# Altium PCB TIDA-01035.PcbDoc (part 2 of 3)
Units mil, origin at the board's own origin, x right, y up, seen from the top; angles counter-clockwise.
Board outline 3937.01 x 2952.76 mil, 4 copper layers (Top Layer, GND, PWR, Bottom Layer), stack 79.834 mil thick; 286 components, 165 nets, 861 pads, 352 vias.
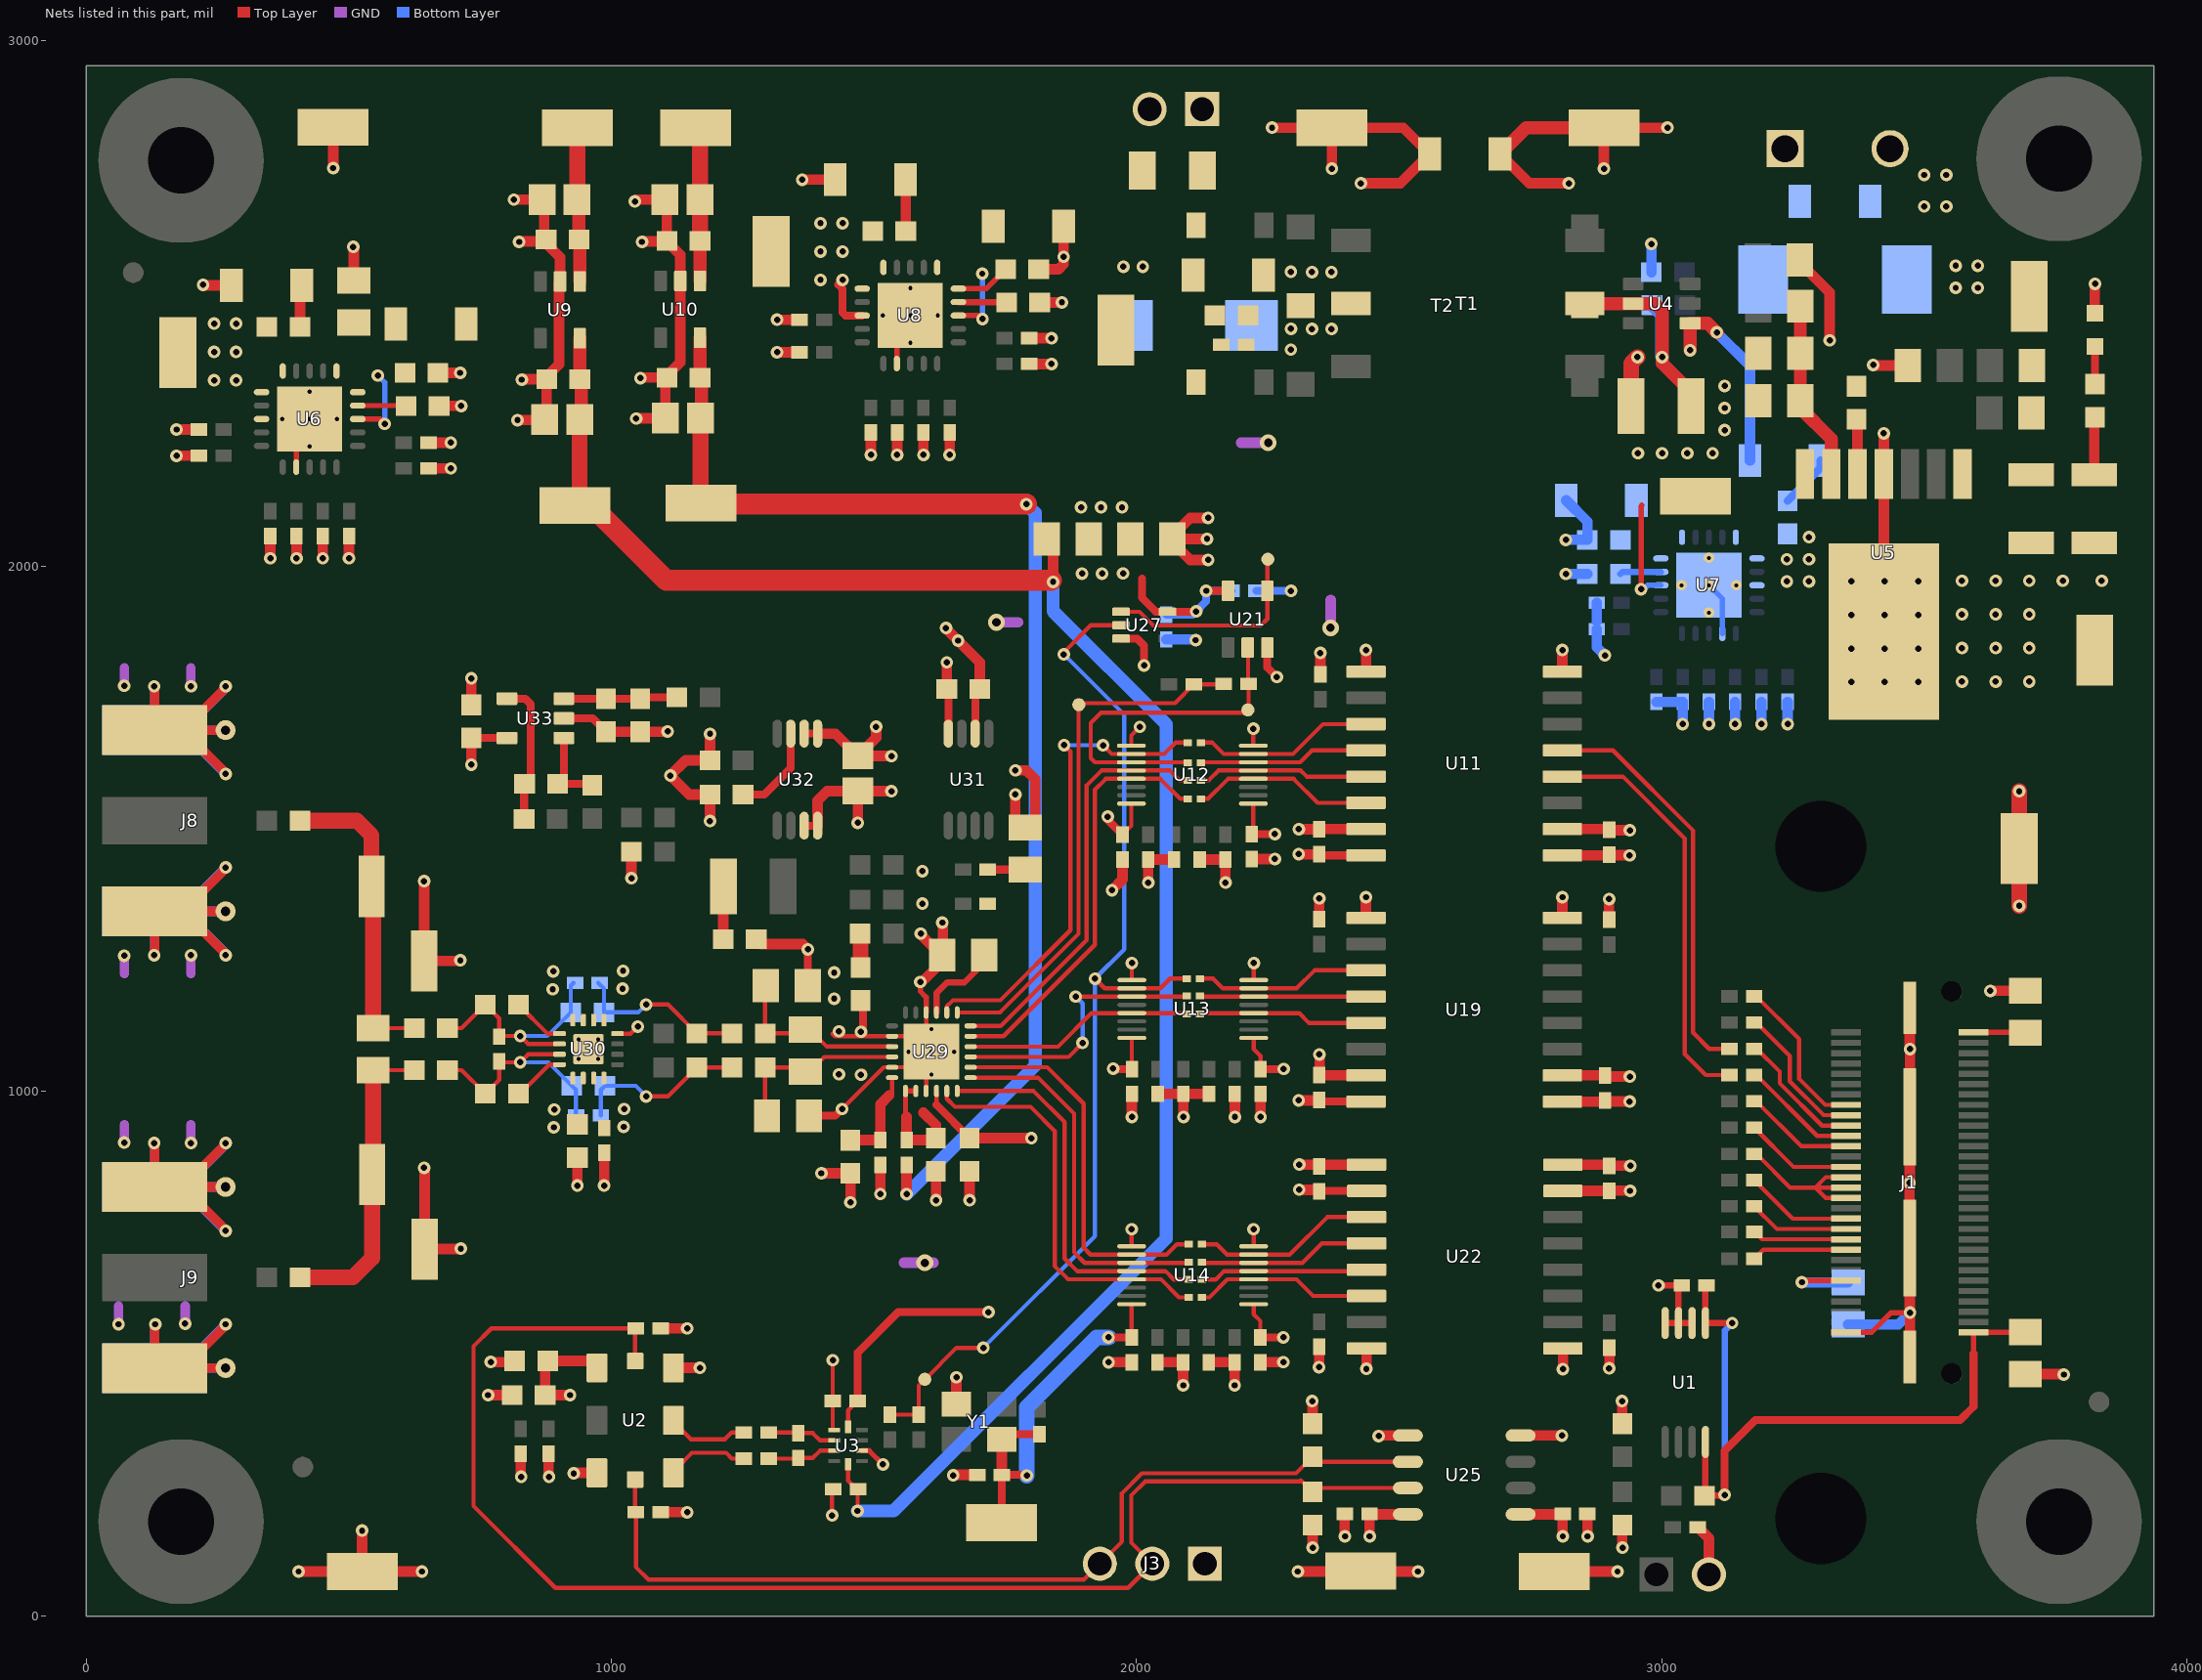
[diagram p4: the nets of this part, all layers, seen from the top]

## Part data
C1 C4 C5 C19 C88 C96: "CAP, CERM, 10 µF, 10 V, +/- 10%, X7R, 0805"
C2 C3 C6 C11 C12 C18 C44 C45 C46 C47 C48 C49 C50 C51 C58 C59 C64 C67 C68 C73 C74 C77 C90: "CAP, CERM, 0.1 µF, 16 V, +/- 10%, X7R, 0402"
C7 C97: "CAP, CERM, 0.1 µF, 25 V, +/- 5%, X7R, 0603"
C8 C89: "CAP, CERM, 10 µF, 10 V, +/- 10%, X7T, 0603"
C9 C10: "CAP, CERM, 0.1 µF, 25 V, +/- 10%, X5R, 0402"
C13: library part 293D107X9020E2TE3, "100µF ±10% Molded Tantalum Capacitors 20V 2917 (7343 Metric) 35 mOhm"
C14 C24: "CAP, CERM, 10 µF, 25 V, +/- 20%, X7R, 1206_190"
C15 C25 C28 C30 C32 C33: "CAP, CERM, 47 µF, 25 V, +/- 20%, X5R, 1206_190"
C16 C29 C31 C82 C86: "CAP, CERM, 1000 pF, 50 V, +/- 1%, C0G/NP0, 0603"
C17 C26 C34 C35 C79 C80 C92 C94 C95 C100 C101: "CAP, CERM, 1 µF, 25 V, +/- 10%, X7R, 0603"
C20: "CAP, CERM, 0.022uF, 50V, +/-10%, X7R, 0805"
C21: library part C3225X5R1A226M, "CAP, CERM, 22uF, 10V, +/-20%, X5R, 1210"
C22 C23: library part UMK325AB7106KM-T, "10µF ±10% 50V Ceramic Capacitor X7R 1210 (3225 Metric)"
C27: "CAP, CERM, 0.01uF, 50V, +/-5%, X7R, 0603"
C36 C40: "CAP, CERM, 1uF, 50V, +/-10%, X7R, 0805"
C37 C39 C41 C43: "CAP, CERM, 0.1uF, 50V, +/-10%, X7R, 0603"
C38 C42: "CAP, CERM, 10uF, 16V, +/-20%, X5R, 0805"
C75: "CAP, CERM, 1000 pF, 2000 V, +/- 10%, X7R, 1206_190"
C76 C83 C93: "CAP, CERM, 100 pF, 50 V, +/- 5%, C0G/NP0, 0402"
C81 C91: "CAP, CERM, 470 pF, 100 V, +/- 5%, C0G/NP0, 0805"
C84: "CAP, CERM, 0.01 µF, 100 V, +/- 1%, C0G/NP0, 0805"
C85: "CAP, CERM, 1000 pF, 100 V, +/- 5%, C0G/NP0, 0805"
C87: "CAP, CERM, 22 µF, 6.3 V, +/- 20%, X5R, 0603"
C98: "CAP, CERM, 47 µF, 10 V, +/- 10%, X7R, 1210"
C99: "CAP, CERM, 10uF, 10V, +/-10%, X7R, 0805"
C102: "CAP, CERM, 1uF, 10V, +/-10%, X7R, 0603"
D1 D3: "Diode, Schottky, 20 V, 0.5 A, SOD-123"
D2: "Diode, Schottky, 200V, 4A, SMC"
D4: "LED, Red, SMD"
FID1 FID2 FID3 FID4 FID5 FID6: "Fiducial mark.  There is nothing to buy or mount."
H1 H2 H3 H4: library part "NY PMS 440 0025 PH", "Machine Screw, Round, #4-40 x 1/4, Nylon, Philips panhead"
H5 H6 H7 H8: "Standoff, Hex, 0.5\"L #4-40 Nylon"
H13 H14: "ROUND STANDOFF M3 STEEL 11MM"
J1: library part QTH-030-01-L-D-A, "Header(Shrouded), 19.7mil, 30x2, Gold, SMT"
J2 J4: "Header, 2.54 mm, 2x1, Gold, TH"
J3: "Header, 2.54 mm, 3x1, Gold, TH"
J5: library part 691213510002, "2 Position Wire to Board Terminal Block Horizontal with Board 0.197\" (5.00mm) Through Hole"
J7 J11: library part 87898-0204, "Header, 2.54 mm, 2x1, Gold, R/A, SMT"
J8 J9: "Connector, End launch SMA, 50 ohm, SMT"
Logo1: library part ESD_Susceptible, "ESD Susceptible Symbol"
Logo2: library part Pb-Free
Logo3: library part FCC_disclaimer, "FCC_disclaimer"
R1 R2 R3 R4 R5 R7 R8 R9 R10 R11 R12 R27 R28 R29 R30 R32 R33 R35 R37 R41 R42 R43 R44 R45 R46 R47 R48 R49 R50 R51 R52 R53 R54 R55 R56 R81 R87 R91 R102: "RES, 0, 5%, 0.063 W, 0402"
R6: "RES, 10.0 k, 1%, 0.1 W, 0603"
R13 R14 R17: "RES, 33, 5%, 0.063 W, 0402"
R15 R16 R20 R21: "RES, 4.7 k, 5%, 0.063 W, 0402"
R18 R59 R64 R65 R69 R70 R90 R105 R106 R107 R108 R109 R110 R111 R112 R113 R114 R115: "RES, 10.0 k, 1%, 0.1 W, 0402"
R19: "RES, 100, 1%, 0.063 W, 0402"
R22: "RES, 0, 5%, 0.25 W, 1206"
R23 R38 R39: "RES, 0.1, 1%, 0.1 W, 0603"
R24: "RES, 118 k, 1%, 0.125 W, 0805"
R25: library part RT0805BRD075K62L, "RES, 5.62 k, 0.1%, 0.125 W, 0805"
R26: "RES, 249k ohm, 1%, 0.125W, 0805"
R31: "RES, 549, 0.5%, 0.1 W, 0805"
R34: "RES, 20.5 k, 1%, 0.125 W, 0805"
R36: "RES, 392, 0.5%, 0.1 W, 0805"
R40: "RES, 1.2 k, 5%, 0.1 W, 0603"
R57 R58 R60 R61 R62 R63 R66 R67 R68 R71 R76: library part CRCW04020000Z0ED, "RES SMD 0.0OHM JUMPER 1/20W 0201"
R72 R73 R74 R75: "RES, 1.5 k, 5%, 0.1 W, 0603"
R77 R82 R83 R92: "RES, 1.00 k, 0.1%, 0.1 W, 0603"
R78 R80 R84 R86 R88 R98 R103 R104: "RES, 0, 5%, 0.1 W, 0603"
R79 R89: library part RT0603BRD0722R1L, "RES SMD 22.1 OHM 0.5% 1/16W 0603"
R85: "RES, 1.00, 1%, 0.1 W, 0603"
R93: "RES, 0.22, 1%, 0.125 W, 0402"
R94: "RES, 20.0 k, 0.1%, 0.1 W, 0603"
R95: "RES, 1.00 k, 1%, 0.1 W, 0603"
R96: "RES, 499, 0.1%, 0.1 W, 0603"
R97 R101: "RES, 49.9 k, 0.1%, 0.1 W, 0603"
R99 R100: "RES, 0.22 ohm, 1%, 0.1W, 0603"
R116 R117: "RES, 0, 5%, 0.125 W, 0805"
T1: "Transformer, 340 uH, TH"
T2: "Transformer, 110 uH, SMT"
TP1 TP20 TP21 TP22: "Test Point, O.025\""
TP2 TP3 TP4 TP5 TP6 TP7 TP8 TP9 TP10 TP11 TP12 TP13 TP14 TP15 TP16 TP17 TP18 TP19: "Test Point, Miniature, SMT"
U1: "I2C BUS EEPROM (2-Wire), TSSOP-B8"
U2: library part LMK61E2-SIAR, "Ultra-Low Jitter Programmable Oscillator with Internal EEPROM, SIA0008B"
U3: "500 Mbps High-Speed Differential Line Driver / Receivers with LVDS Input and LVTTL / LVCMOS Output, 1 Rx, -40 to +85 degC, 10-pin UQFN (RSE), Green (RoHS & no Sb/Br)"
U4: "LOW-NOISE 1A TRANSFORMER DRIVERS FOR ISOLATED POWER SUPPLIES, DBV0006A"
U5: "3A SIMPLE SWITCHER® Power Module with 42V Maximum Input Voltage, 7-pin TO-PMOD, Pb-Free"
U6 U7 U8: "36-V, 1-A, 4.17-µVRMS, RF LDO Voltage Regulator, RGW0020A"
U9 U10: library part TPS70933DBVT, "IC REG LDO 1.8V 0.15A SOT23-5"
U11 U22: library part ISO7840DWR, "High-Performance, 8000 VPK Reinforced Quad-Channel Digital Isolator, DW0016B"
U12 U13 U14: "4-Bit Dual-supply Bus Transceiver with Configurable Voltage Translation and 3-State Outputs, DGV0016A"
U19: "High-Performance, 8000 VPK Reinforced Quad Channel Digital Isolator, DW0016B"
U21: "SINGLE SCHMITT-TRIGGER INVERTER GATE, DBV0005A"
U25: "Low-Power Bidirectional I2C Isolators, D0008A"
U27: library part SN74AUP1G80DCK, "IC, Single Positive-Edge-Triggered D-Type Flip-Flop"
U29: library part ADS9110IRGER, "18-Bit, 2-MSPS, 20-mW, SAR ADC with Enhanced Serial Interface, RGE0024H"
U30: "Low Power, Precision, 160MHz, Fully Differential Amplifier, RGT0016A"
U31: "Low Noise, Very Low Drift, Precision Voltage Reference, -40 to 125 degC, 8-pin VSSOP (DGK), Green (RoHS & no Sb/Br)"
U32: library part REF6025AIDGK, "High-Precision Voltage Reference with Integrated High-Bandwidth Buffer, DGK0008A"
U33: "Precision, Low Noise, Low Iq Operational Amplifier, 2.2 to 5.5 V, -40 to 125 degC, 5-pin SOT23 (DBV0005A), Green (RoHS & no Sb/Br)"
Y1: library part AU-40.000MDE-T, "OSC, 125 MHz, 3.3V, SMD"
ZZ1 ZZ2 ZZ3: library part AssemblyNote

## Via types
v1: diameter 24, hole 12, Top Layer to Bottom Layer, tented both sides, 324 vias
v2: diameter 19.68, hole 7.87, Top Layer to Bottom Layer, 24 vias
v3: diameter 32, hole 16, Top Layer to Bottom Layer, 4 vias

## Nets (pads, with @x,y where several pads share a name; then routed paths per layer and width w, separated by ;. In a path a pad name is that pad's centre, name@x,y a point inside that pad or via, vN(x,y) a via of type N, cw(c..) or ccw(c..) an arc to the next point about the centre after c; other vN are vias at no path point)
1P8V_ISO: C11.1 C38.1 C39.1 R117.2 TP8.1 U3.5 U9.5 | length 3618.5
  Top Layer w8: U3.5@1450.51,289.57 1450.51,258.11 1468.62,240 v1(1468.62,200.38)
  Top Layer w20: R117.2@1829.18,2051.77 1841,2039.95 v1(1841,1970) v1@1838,1973
  Top Layer w25: C39.1@939.4,2356.09 U9.5@939.4,2433.87 ; C38.1@942.56,2279.34 C39.1@942.56,2355.37
  Top Layer w30: C38.1@939.46,2279 939.46,2124.46 TP8.1@930,2115 TP8.1@962,2115
  Top Layer w40: TP8.1@962,2115 1104,1973 v1@1838,1973
  Bottom Layer w25: v1(1468.62,200.38) 1537.38,200.38 2056.18,719.18 2056.18,1698.77 1841,1913.95 v1(1841,1970)
3P3V: C44.2 C58.2 C68.1 C73.2 R38.2 R64.1 R69.2 R72.2 R74.2 TP6.1 U7.1 U7.3 U7.20 U11.1 U19.1 U22.16 U25.1 | length 898.7
  Top Layer w15: C68.1@2898.62,860 C68.1@2901,857.62
  Top Layer w20: U25.1@2731.28,194 2810.38,194 C73.2@2811.38,195 2811.38,151.62 v1(2811.76,152) ; U19.1@2811.01,980 2899.62,980 2900,980.38 2938.62,980.38 v1(2939,980) ; U11.1@2811.01,1449 2899.62,1449 2900,1449.38 2938.62,1449.38 v1(2939,1449) ; U22.16@2812.01,860 C68.1@2898.62,860 ; v1(2900,472) 2900.38,472.38 2900.38,511 R69.2@2900,511.38 ; R64.1@2900,1326.62 2899.62,1327 2899.62,1365.62 v1(2900,1366) ; C68.1@2901,857.62 2901.38,858 2940,858 v1(2940.38,857.62) ; R74.2@2924,367.5 R74.2@2925,366.5 2925,409.87 v1(2924.62,409.5) ; v1(2925.38,130.5) 2925,130.13 R72.2@2925,173.5 R72.2@2926,172.5
  Top Layer w30: v1(3681,1353) TP6.1@3681,1462 v1(3681,1571)
  other v1: 3238.5,1971 3280.5,1971 3238.5,2013 3280.5,2013 3280.5,2055
3P3V_ISO: C7.1 C8.1 C45.1 C46.1 C48.1 C50.1 C59.1 C67.2 C74.1 R15.2 R16.2 R18.2 R21.1 R39.2 R59.2 R65.2 R70.1 R73.2 R75.2 R105.2 R108.2 R116.2 TP7.1 U2.1@972.17,473 U2.6@1117.83,473 U8.1 U8.3 U8.20 U11.16 U12.1 U13.1 U14.1 U19.16 U22.1 U25.8 | length 1925.8
  Top Layer w8: C46.1@2219.18,1489.39 2222.32,1492.54 U12.1@2222.32,1547.65 ; U14.1@2222.82,594.15 2222.82,575.13 2235.68,562.27 C50.1@2235.68,530.89 ; U13.1@2223.18,1101.28 2223.18,1079.77 2236.04,1066.91 C48.1@2236.04,1042.02
  Top Layer w15: 1432,2536 1440,2528 1440,2483 1445.73,2477.27 U8.3@1477.46,2477.27 ; C46.1@2219.18,1489.39 v1@2263.05,1489.39 ; C50.1@2235.68,530.89 v1@2279.55,530.89 ; C48.1@2236.04,1042.02 v1@2279.91,1042.02 ; C59.1@2348,982.38 2350.38,980 U19.16@2436.99,980 ; C45.1@2348,1451.38 2350.38,1449 U11.16@2436.99,1449
  Top Layer w20: R21.1@827,309.38 827,266.21 v1(828,265.21) ; v1(921,421) C7.1@873.5,421 873.5,481 C8.1@878.5,486 959.17,486 U2.1@972.17,473 ; R16.2@1093.62,198 v1(1144,198) ; R15.2@1093.62,548 v1(1144,548) ; U2.6@1117.83,473 v1(1168.21,473) ; R18.2@2120.18,1441.15 R105.2@2169.18,1441.15 2169.18,1397.28 v1(2169.32,1397.14) ; v1(2134.18,2051.77) R116.2@2068.18,2051.77 ; v1(2136.18,2011.77) 2102.18,2011.77 2068.18,2045.77 R116.2@2068.18,2051.77 ; v1(2136.18,2091.77) 2102.18,2091.77 2068.18,2057.77 R116.2@2068.18,2051.77 ; R108.2@2187.04,994.78 2187.04,950.91 v1(2187.18,950.77) ; v1@2263.05,1489.39 v1(2263.19,1489.54) ; v1@2279.55,530.89 v1(2279.69,531.04) ; v1@2279.91,1042.02 v1(2280.05,1042.17) ; v1(2308.62,982.38) 2309,982 2347.62,982 C59.1@2348,982.38 ; v1(2308.62,1451.38) 2309,1451 2347.62,1451 C45.1@2348,1451.38 ; v1(2310,860) 2310.38,859.62 2349,859.62 2349.38,860 U22.1@2437.99,860 ; R73.2@2334,367.5 R73.2@2335,366.5 2335,409.87 v1(2334.62,409.5) ; v1(2335.38,130.5) 2335,130.13 R75.2@2335,173.5 R75.2@2336,172.5 ; v1(2347.62,474.38) 2348,474.76 R70.1@2348,513.38 R70.1@2347.62,513.76 ; R65.2@2348,1327.62 2347.62,1328 2347.62,1366.62 v1(2348,1367) ; R59.2@2350,1793.62 v1(2350,1834.63) ; v1(2444,152) 2443.62,151.62 C74.1@2443.62,195 2444.62,194 U25.8@2516.72,194
  other v1: 1398,2545 1440,2545 1398,2599 1440,2599 1398,2653 1440,2653
5V_ISO: C89.1 C90.2 C94.1 C97.2 C99.2 R23.2 R91.2 TP2.1 U6.1 U6.3 U6.20 U30.5 U30.6 U30.7 U30.8 U30.12 U31.2 U32.1 U32.2 U33.5 | length 703.8
  Top Layer w8: U30.12@1011.12,1109.53 1036.53,1109.53 v1(1050,1123)
  Top Layer w15: v1(732.94,1621.94) v1@733,1622 ; C97.2@733,1672.5 733.09,1672.6 U33.5@800.87,1672.6 ; U32.2@1366.86,1680.88 U32.1@1392.45,1680.88 ; U31.2@1692.65,1680.88 1692.65,1757.15 C94.1@1701.5,1766
  Top Layer w20: v1@733,1622 C97.2@733,1672.5 ; U32.1@1392.45,1680.88 1426.58,1680.88 C99.2@1469,1638.46 ; v1(1504,1694) 1504,1673.46 C99.2@1469,1638.46 ; v1(1512,804) R91.2@1512,859.38 ; v1(1533,1638) 1532.54,1638.46 C99.2@1469,1638.46 ; v1(1637,1882) 1637,1881 v1(1660,1858) 1701.5,1816.5 C94.1@1701.5,1766
  other v1: 890,931 1023,932 891,965 1024,966 243.07,2353.86 285.07,2353.86 243.07,2407.86 285.07,2407.86 243.07,2461.86 285.07,2461.86
5VDC: C20.1 C21.1 C28.1 C29.1 R25.2 R103.2 T1.2 T2.2 TP5.1 U4.2 U5.7 U7.13 U7.15 U7.16 | length 665
  Top Layer w10: v1(2961,1956) 2961,2115 2962,2116
  Top Layer w25: T1.2@2853.64,2500 U4.2@2945.87,2500 2987,2500 3001,2486 v1(3001,2398) 3001,2386.15 3056.09,2331.06 C21.1@3056.09,2305
  Bottom Layer w10: v1(2961,1956) 2966,1956 2973.35,1963.35 U7.13@2998.46,1963.35
  Bottom Layer w25: R103.2@2981.5,2497 3000,2478.5 3000,2399 v1(3001,2398)
  other v1: 2955,2215 3001,2215 3049,2215 3097,2215 3120,2259 3120,2301 3120,2343
+12VDC: C22.1 C23.1 D2.1 R24.2 R26.2 R40.2 TP4.1 U5.1 | length 110
  Top Layer w20: C23.1@3824,2173.96 3824,2282.5 R40.2@3825,2283.5
  other v1: 3560,2530 3602,2530 3560,2572 3602,2572
+12VDC_IN: C24.1 D2.2 J5.1
A1P8V_ISO: C42.1 C43.1 R81.1 TP9.1 U10.5 | length 2412.8
  Top Layer w20: TP9.1@1169.46,2120.54 TP9.1@1170,2120 TP9.1@1172,2118 ; v1(1562,804) R81.1@1562,859.38
  Top Layer w25: C43.1@1168.4,2359.09 U10.5@1168.4,2434.87 ; C42.1@1171.56,2282.34 C43.1@1171.56,2358.37
  Top Layer w30: TP9.1@1169.46,2120.54 C42.1@1169.46,2282
  Top Layer w40: TP9.1@1172,2118 v1(1790,2118)
  Bottom Layer w25: v1(1562,804) 1807,1049 1807,2101 v1(1790,2118)
ADC_CONVST: R62.2 R87.2 TP22.1 U12.11 U21.2 | length 684.7
  Top Layer w8: R62.2@2097.68,1625.77 2097.06,1626.39 U12.11@1990.04,1626.39 1920.56,1626.39 1912.68,1634.27 1912.68,1701.27 1932.18,1720.77 2206.77,1720.77 TP22.1@2212,1726 2213.2,1727.2 R87.2@2213.2,1775.91 2212.23,1775.91 U21.2@2212.23,1844.13
ADC_CONVST1: R87.1 R102.1 TP21.1 U29.1 | length 1022.5
  Top Layer w8: U29.1@1658.28,1149.74 1739.74,1149.74 1889.5,1299.5 1889.5,1735.5 TP21.1@1890,1736 1892.77,1738.77 2073.07,1738.77 R102.1@2109.2,1774.91 2164.96,1774.91 R87.1@2165.96,1775.91
ADC_CONVSTN: TP20.1 U21.4 U27.1 | length 408.6
  Top Layer w8: U27.1@1970.42,1913 2005.49,1913 2031.58,1886.91 2236.58,1886.91 2248.98,1899.31 U21.4@2248.98,1953.04 2248.98,2011.98 TP20.1@2250,2013
ADC_CSN: R68.2 U12.12 U29.24 | length 795.7
  Top Layer w8: U29.24@1683.87,1124.15 1741.15,1124.15 1905,1288 1905,1582.59 1933.06,1610.65 U12.12@1990.04,1610.65 2063.31,1610.65 2082.18,1591.77 R68.2@2097.68,1591.77
ADC_RESETN: R57.2 U12.10 U29.2 | length 916.3
  Top Layer w8: U29.2@1638.59,1149.74 1638.59,1161.59 1650.05,1173.05 1665,1173.05 1665.05,1173 1740.37,1173 1874,1306.63 1874,1647 v1(1862,1659) ; v1(1936.18,1658.77) 1952.81,1642.14 U12.10@1990.04,1642.14 2052.55,1642.14 2074.18,1663.77 R57.2@2097.68,1663.77
  Bottom Layer w8: v1(1862,1659) 1862.23,1658.77 v1(1936.18,1658.77)
ADC_RVS: R76.2 U13.11 U29.21 | length 530.2
  Top Layer w8: U29.21@1683.87,1065.09 1870.5,1065.09 v1(1897.18,1091.77) ; v1(1884.02,1180.02) U13.11@1990.9,1180.02 2094.16,1180.02 R76.2@2095.54,1181.4
  Bottom Layer w8: v1(1884.02,1180.02) 1897.18,1166.87 v1(1897.18,1091.77)
ADC_SCLK: R60.2 U12.13 U29.23 | length 805.9
  Top Layer w8: U29.23@1683.87,1104.46 1746.46,1104.46 1920.5,1278.5 1920.5,1574.09 1941.31,1594.9 U12.13@1990.04,1594.9 2045.06,1594.9 2083.18,1556.77 R60.2@2097.68,1556.77
ADC_SDI: R67.2 U13.13 U29.22 | length 438.5
  Top Layer w8: U29.22@1683.87,1084.78 1850.19,1084.78 1913.94,1148.53 U13.13@1990.9,1148.53 2094.41,1148.53 R67.2@2095.54,1147.4
ADC_SDO0: R66.2 U14.10 U29.20 | length 731.7
  Top Layer w8: U29.20@1683.87,1045.41 1829.59,1045.41 1899,976 1899,702 1912.36,688.64 U14.10@1990.54,688.64 2057.05,688.64 2076.68,708.27 R66.2@2099.18,708.27
ADC_SDO1: R58.2 U14.11 U29.19 | length 716.7
  Top Layer w8: U29.19@1683.87,1025.72 1812.28,1025.72 1881,957 1881,693 1901.11,672.89 U14.11@1990.54,672.89 2097.8,672.89 R58.2@2099.18,674.27
ADC_SDO2: R61.2 U14.12 U29.18 | length 741.9
  Top Layer w8: U29.18@1658.28,1000.13 1803.87,1000.13 1863,941 1863,681 1886.85,657.15 U14.12@1990.54,657.15 2054.81,657.15 2070.68,641.27 R61.2@2099.18,641.27
ADC_SDO3: R63.2 U14.13 U29.17 | length 782.5
  Top Layer w8: U29.17@1638.59,1000.13 1638.59,985.41 1654,970 1798,970 1844,924 1844,667 1869.6,641.4 U14.13@1990.54,641.4 2046.56,641.4 2080.68,607.27 R63.2@2099.18,607.27
ADC_SYSCLK: R14.2 R17.2 R71.2 TP1.1 U13.10 U27.2 | length 2068.6
  Top Layer w8: R17.2@1530,383.62 R14.2@1585,383.62 1585,439.36 TP1.1@1596.64,451 ; TP1.1@1597,451 1657,511 v1(1708,511) ; v1(1861.18,1831.77) 1861.18,1835.77 1912.82,1887.41 U27.2@1970.42,1887.41 ; v1(1920.68,1214.27) 1939.18,1195.77 U13.10@1990.9,1195.77 2045.18,1195.77 2063.81,1214.4 R71.2@2095.54,1214.4 ; U27.2@1970.42,1887.81 U27.2@1971.18,1887.81
  Bottom Layer w8: v1(1708,511) 1920.68,723.68 v1(1920.68,1214.27) 1976.68,1270.27 1976.68,1716.27 v1(1861.18,1831.77)
AGND_ISO: C6.2 C7.2 C8.2 C11.2 C12.2 C13.2 C14.2 C15.2 C16.2 C17.2 C18.1 C19.2 C25.2 C26.1 C30.2 C31.2 C33.2 C35.1 C36.2 C37.2 C38.2 C39.2 C40.2 C41.2 C42.2 C43.2 C45.2 C46.2 C47.2 C48.2 C49.2 C50.2 C51.2 C59.2 C64.1 C67.1 C74.2 C75.1 C77.1 C79.1 C80.2 C81.2 C87.2 C88.2 C89.2 C90.1 C91.2 C92.2 C94.2 C96.2 C97.1 C99.1 C100.2 C101.2 C102.2 J3.1 J7.1 J8.2 J8.3 J8.4 J8.5 J9.2 J9.3 J9.4 J9.5 J11.1 R20.1 R27.1 R28.1 R29.1 R30.1 R32.1 R33.1 R35.1 R37.1 R42.1 R44.1 R46.1 R48.1 R50.1 R52.1 R54.1 R56.1 R99.2 R100.1 R101.1 R106.1 R107.1 R109.1 R110.1 R111.1 R112.1 R113.1 R114.1 R115.1 T1.5 T2.5 TP12.1 TP13.1 TP18.1 TP19.1 U2.3@972.17,273 U3.1 U3.7 U6.7 U6.21 U8.7 U8.21 U9.2 U10.2 U11.9 U11.15 U12.8 U12.9 U13.8 U13.9 U14.8 U14.9 U19.9 U19.15 U21.3 U22.2 U22.8 U25.5 U27.3 U29.4 U29.8 U29.11 U29.15 U29.25 U30.13 U30.14 U30.15 U30.16 U30.17 U31.4 U32.7 U32.8 U33.2 Y1.2 | length 12006.7
  Top Layer w8: v1(1420,192) 1420,238.62 C11.2@1421.38,240 ; 1420.79,1109.21 1425.54,1104.46 U29.8@1534.26,1104.46 1579.54,1104.46 U29.25@1599.22,1084.78 ; C12.2@1421,409.62 C12.2@1421.38,410 ; v1(1421.38,487.62) C12.2@1421.38,410 ; U3.1@1423.94,354.53 1421.38,357.09 C12.2@1421.38,410 ; v1(1439,966) 1518.41,1045.41 U29.11@1534.26,1045.41 1579.54,1045.41 U29.25@1599.22,1065.09 ; U29.15@1599.22,1000.13 U29.25@1599.22,1065.09 ; U29.4@1599.22,1149.74 U29.25@1599.22,1084.78 ; U12.9@1990.04,1657.89 1990.04,1677.63 v1(2006.18,1693.77) ; U14.9@1990.54,704.39 v1(1990.54,736.93) ; U13.9@1990.9,1211.52 v1(1990.9,1244.06) ; U12.8@2222.32,1657.89 v1(2222.32,1690.43) ; U14.8@2222.82,704.39 v1(2222.82,736.93) ; U13.8@2223.18,1211.52 v1(2223.18,1244.06) ; U29.25@1599.22,1065.09 v2(1609.06,1074.94) U29.25@1599.22,1084.78
  Top Layer w10: U6.7@399.47,2188.53 399.47,2254.47 v2(425.06,2280.06) ; U3.7@1477.09,315.16 1490.55,315.16 1516.71,289 v1(1517,289) ; U8.7@1543.41,2385.73 U8.21@1543.41,2451.68 ; v1(1588,1208) 1588,1190.22 1599.22,1179 U29.4@1599.22,1149.74
  Top Layer w15: v1@733,1786 v1(733.06,1786.06) ; U33.2@909.13,1710 964.01,1710 C101.2@989.5,1684.5 ; v1(1037.94,1405.43) v1@1038.01,1405.5 ; v1(1187.5,1514.37) v1@1187.57,1514.43 ; v1@1187.57,1680.44 v1(1187.63,1680.5) ; U32.7@1366.86,1505.68 U32.8@1392.45,1505.68 ; C81.2@1374,1201 v1(1374,1270) ; C91.2@1376,953 1426,953 v1(1439,966) ; v1(1475,1031) v1@1479,1035 ; v1(1475,1113) 1479,1117 C87.2@1479,1172.5 ; U8.21@1543.41,2451.68 v2(1569,2477.27) ; C94.2@1638.5,1766 1641.46,1763.04 U31.4@1641.46,1680.88 ; v1@1638.5,1816.5 v1(1638.57,1816.57) ; U27.3@1970.42,1861.82 2001.13,1861.82 2014.18,1848.77 v1(2014.18,1810.77) ; U21.3@2248.98,1849.71 U21.3@2248.98,1844.77 2248.98,1806.97 v1(2267.18,1788.77) ; C67.1@2349,812.38 2351.38,810 U22.2@2437.99,810
  Top Layer w18: J9.2@130,472.5 v1@130,555 ; J9.3@130,817.5 v1@130,900 ; v1@130,1260 J8.2@130,1342.5 ; J8.3@130,1687.5 v1@130,1770 ; J9.2@183.5,472.5 265,554 v1(265,556) ; v1(265,734) 265,736 183.5,817.5 v1@265,899 ; v1@265,1261 183.5,1342.5 265,1424 v1(265,1426) ; v1(265,1604) 265,1606 183.5,1687.5 v1@265,1769
  Top Layer w20: v1(171.55,2210.06) R28.1@213.82,2210.06 ; v1(171.55,2260.06) R27.1@213.82,2260.06 ; v1(222.07,2535.86) 223.07,2534.86 C25.2@276.14,2534.86 ; v1(350.06,2014.8) R29.1@350.06,2057.06 ; v1(400.06,2014.8) R30.1@400.06,2057.06 ; v1(404,85) TP18.1@525,85 ; v1(450.06,2014.8) R32.1@450.06,2057.06 ; v1(470,2758) TP13.1@470,2836 ; v1(500.06,2014.8) R33.1@500.06,2057.06 ; v1(508,2608) 509,2607 C19.2@509,2544 ; v1(525,163) TP18.1@525,85 ; v1(639,85) TP18.1@525,85 ; v1(643,854) 644,853 J11.1@644,699.13 712.13,699.13 v1(713,700) ; v1(643,1400) J7.1@643,1248.13 711.13,1248.13 v1(712,1249) ; R35.1@651.69,2186.06 v1(693.95,2186.06) ; R37.1@651.69,2235.06 v1(693.95,2235.06) ; C16.2@669.56,2368.06 v1(711.83,2368.06) ; C26.1@671.56,2305.06 v1(713.83,2305.06) ; C97.1@733,1735.5 v1@733,1786 ; v1(765,421) C7.2@810.5,421 ; v1(770,484) 813.5,484 C8.2@815.5,486 ; v1(814,2698) C36.2@867.54,2698 871.5,2694.03 C37.2@871.5,2618.46 ; v1(820.97,2278) 821.43,2278.46 C38.2@876.5,2278.46 ; v1(823.97,2617.46) 824.97,2618.46 C37.2@871.5,2618.46 ; v1(828.97,2355) 829.97,2356 C39.2@876.5,2356 ; C37.2@871.5,2618.15 C37.2@871.5,2618.46 ; C37.2@874.47,2618.46 C37.2@871.5,2618.46 ; C37.2@875.5,2622 875.5,2614.46 902,2587.97 U9.2@902,2542.13 900,2540.13 900,2384.54 876.5,2361.05 C39.2@876.5,2356 ; C38.2@879.47,2278.46 C38.2@876.5,2278.46 ; R20.1@880,309.38 880,266.21 v1(881,265.21) ; v1(928,272) 929,273 U2.3@972.17,273 ; v1(935,820) C89.2@935,873.5 ; v1(986,820) C90.1@986,882.38 ; C101.2@989.5,1684.5 R101.1@1054.5,1684.5 1106.5,1684.5 v1(1107,1685) ; v1@1038.01,1405.5 C100.2@1038.01,1456 ; v1(1044.46,2694.46) 1048,2698 C40.2@1101.54,2698 1105.5,2694.03 C41.2@1105.5,2619 C41.2@1105.5,2618.46 ; v1(1047,2281) 1047.46,2281.46 C42.2@1102.54,2281.46 ; v1(1055,2358) 1056,2359 C43.2@1102.54,2359 ; v1(1057.97,2617.46) 1058.97,2618.46 C41.2@1105.5,2618.46 ; C42.2@1105.5,2281.46 C42.2@1102.54,2281.46 ; C43.2@1105.5,2359 C43.2@1102.54,2359 ; C41.2@1108.47,2618.46 C41.2@1105.5,2618.46 ; v1@1187.57,1514.43 C102.2@1187.57,1564.94 1148.06,1564.94 v1(1112,1601) 1140.94,1629.94 R100.1@1187.57,1629.94 v1@1187.57,1680.44 ; R99.2@1275.5,1289 1284.5,1280 1364,1280 v1(1374,1270) ; v1(1315.49,2407.27) R44.1@1357.76,2407.27 ; v1(1315.49,2469.27) R42.1@1357.76,2469.27 ; v1(1363,2736) C33.2@1426.07,2736 ; U32.8@1392.45,1505.68 1392.45,1553.45 1410.54,1571.54 C99.1@1469,1571.54 ; v1(1399.62,843.5) C92.2@1455,843.5 v1(1455,788.13) ; v1(1469,1511) C99.1@1469,1571.54 ; v1(1494,2212) R46.1@1494,2254.27 ; v1(1533,1571.07) 1532.54,1571.54 C99.1@1469,1571.54 ; v1(1544,2212) R48.1@1544,2254.27 ; v1(1588,1208) 1591.22,1208 1631,1247.78 C88.2@1631,1256 ; v1@1590,1297 C88.2@1631,1256 ; v1(1594,2212) R50.1@1594,2254.27 ; v1(1618,792.13) C80.2@1618,847.5 ; v1@1631,1318 C88.2@1631,1256 ; C94.2@1638.5,1766 v1@1638.5,1816.5 ; v1(1644,2212) R52.1@1644,2254.27 ; v1(1650.69,268.31) 1651.69,269.31 1696.06,269.31 C6.2@1696.38,269 ; Y1.2@1656.69,403.46 1656.69,454.69 v1(1657,455) ; v1(1682,792.13) C79.1@1682,847.5 ; v1(1769,1565) 1769,1521 C96.2@1788,1502 1807,1521 1807,1594 1790,1611 v1(1769,1611) ; R54.1@1795.62,2385 v1(1837.89,2385) ; R56.1@1795.62,2434 v1(1837.89,2434) ; C31.2@1813.5,2565.27 1851.27,2565.27 1861,2575 v1(1861,2589) 1861,2647.2 C30.2@1860.93,2647.27 ; C35.1@1815.5,2502.27 v1(1857.76,2502.27) ; v1(1946.67,483.51) 1946.82,483.65 C51.2@1990.68,483.65 ; v1(1953.18,1382.77) 1973.18,1402.77 C47.2@1973.18,1441.15 ; C49.2@1991.04,994.78 1991.04,950.91 v1(1991.18,950.77) ; v1(2022.32,1397.14) 2022.18,1397.28 R106.1@2022.18,1441.15 R107.1@2071.18,1441.15 ; R112.1@2039.68,483.65 R113.1@2088.68,483.65 2088.68,439.78 v1(2088.82,439.64) ; R109.1@2040.04,994.78 R110.1@2089.04,994.78 ; v1(2089.18,950.77) 2089.04,950.91 R110.1@2089.04,994.78 ; R115.1@2137.68,483.65 R114.1@2186.68,483.65 2186.68,439.78 v1(2186.82,439.64) ; R111.1@2138.04,994.78 R110.1@2089.04,994.78 ; C46.2@2219.18,1442.15 2263.05,1442.15 v1(2263.19,1442.29) ; C50.2@2235.68,483.65 2279.55,483.65 v1(2279.69,483.79) ; C48.2@2236.04,994.78 2236.04,950.91 v1(2236.18,950.77) ; v1(2258,2835) TP12.1@2372,2835 ; v1(2307,85) TP19.1@2428,85 ; v1(2309,1499) 2309.38,1498.62 C45.2@2348,1498.62 2348.38,1499 U11.15@2436.99,1499 ; v1(2309.62,812.38) 2310,812 2348.62,812 C67.1@2349,812.38 ; C59.2@2347.62,1031 C59.2@2348,1030.62 ; v1@2347.62,1069.62 v1(2348,1070) 2348.62,1069.38 C59.2@2348.62,1031 ; C59.2@2348.38,1030 U19.15@2436.99,1030 ; v1(2372,2757) TP12.1@2372,2835 ; v1(2396.76,152) 2396.38,151.62 C74.2@2396.38,195 C74.2@2397.38,194 ; TP19.1@2427,86 TP19.1@2428,85 ; v1(2427,2729) 2502.07,2729 C75.1@2558.07,2785 2508.07,2835 TP12.1@2372,2835 ; U19.9@2436.99,1330 2436.61,1330.38 2436.61,1369 v1(2436.99,1369.38) ; U11.9@2436.99,1799 v1(2436.99,1840.01) ; v1(2437.61,471) 2437.99,471.38 U22.8@2437.99,510 U22.8@2437.61,510.38 ; v1(2461,343) 2462,344 U25.5@2516.72,344 U25.5@2517.09,344.38 ; v1(2536,85) TP19.1@2428,85 ; C38.2@876.5,2278.46 C39.2@876.5,2356 ; C42.2@1102.54,2281.46 C42.2@1102.54,2282 C43.2@1102.54,2359 ; C43.2@1102.54,2359 1102.54,2359.54 1131,2388 U10.2@1131,2543.13 1131,2592.65 1105.5,2618.15 C41.2@1105.5,2618.46
  GND w18: v1(61,556) 61,591 ; v1(72,902) 72,936 ; 72,1224 v1(72,1258) ; v1(72,1772) 72,1806 ; v1(188,557) 188,591 ; v1(199,901) 199,936 ; 199,1224 v1(199,1259) ; v1(199,1771) 199,1806
  GND w20: 1557,673 v3(1596.64,673) 1613,673 ; v3(1733.02,1892.98) 1773.98,1892.98 ; 2199,2235 v3(2250.71,2235) ; v3(2369.48,1882.48) 2369.48,1935.48
  Bottom Layer w15: C64.1@2228.2,1952.91 2294.05,1952.91 v1(2294.18,1952.77)
  Bottom Layer w18: v1(129,901) 130,900 J9.5@130,817.5 ; v1(129,1259) 130,1260 J8.4@130,1342.5 ; v1(129,1771) 130,1770 J8.5@130,1687.5 ; J9.4@130,472.5 130,555 v1(131,556) ; J9.4@181.5,472.5 v1(265,556) ; J9.5@181.5,817.5 v1(265,734) ; J8.4@181.5,1342.5 v1(265,1426) ; J8.5@181.5,1687.5 v1(265,1604) ; J9.5@184.5,817.5 v1@265,898 ; J8.4@184.5,1342.5 v1@265,1262 ; J8.5@184.5,1687.5 v1@265,1768
  Bottom Layer w20: C77.1@2056.58,1860.28 2111.2,1860.28 v1(2112.58,1858.91)
  other v1: 265,901 1433,1032 1433,1114 1424,1176 888,1194 1021,1195 1424,1226 889,1228 1022,1229 265,1259 1589,1300 1630,1321 1592,1357 1592,1419 265,1771 2293.79,2412.35 2294,2452 2334.21,2451.65 2371.21,2451.65 2334,2560 2371,2560 2293.79,2560.35
  other v2: 1609.06,1031.63 937.3,1061.3 974.7,1061.3 1565.76,1074.94 1652.37,1074.94 937.3,1098.7 974.7,1098.7 1609.06,1118.24 425.06,2227.9 372.9,2280.06 477.23,2280.06 425.06,2332.23 1569,2425.1 1516.83,2477.27 1621.17,2477.27 1569,2529.43
BCLK_N: C10.1 U2.5@1117.83,373 | length 156
  Top Layer w8: U2.5@1117.83,373 1124.83,366 1124.83,363.17 1151,337 1216.14,337 1229.14,350 C10.1@1251.89,350
BCLK_P: C9.1 U2.4@1117.83,273 | length 156
  Top Layer w8: U2.4@1117.83,273 1124.83,280 1124.83,282.83 1153,311 1218.14,311 1229.14,300 C9.1@1251.89,300
CONVST: R3.1 U11.5 | length 778.9
  Top Layer w8: U11.5@2811.01,1649 2907,1649 3060,1496 3060,1111 3090.45,1080.55 R3.1@3128.88,1080.55
CSN: R4.1 U11.4 | length 793.9
  Top Layer w8: U11.4@2811.01,1599 2926,1599 3044,1481 3044,1070.37 3083.83,1030.55 R4.1@3128.88,1030.55
DVDD_ISO: C6.1 C12.1 C47.1 C49.1 C51.1 C64.2 C77.2 C79.2 R13.2 R116.1 R117.1 TP17.1 U3.10 U12.16 U13.16 U14.16 U21.5 U27.5 U29.16 Y1.4 | length 1948.5
  Top Layer w8: U3.10@1450.51,360.43 1450.51,391.89 C12.1@1468.62,410 ; 1618.91,973.59 U29.16@1618.91,1000.13 ; v1@1945.18,1516.39 v1(1945.18,1522.77) ; v1(1955.18,1042.77) v1@1955.93,1042.02 ; C47.1@1973.18,1488.39 1990.04,1505.25 U12.16@1990.04,1547.65 ; U14.16@1990.54,594.15 1990.54,531.04 C51.1@1990.68,530.89 ; U13.16@1990.9,1101.28 1990.9,1042.17 C49.1@1991.04,1042.02
  Top Layer w15: C12.1@1468.62,410 1468.62,501.62 1546,579 v1(1718,579) ; 1618.91,973.59 C79.2@1682,910.5 ; TP17.1@1743,178 C6.1@1743,269.01 ; C6.1@1743.62,269 1790,269 v1(1791,268) ; Y1.4@1753.15,346.38 R13.2@1815,346.38 ; v1@1945.18,1516.39 C47.1@1973.18,1488.39 ; v1@1946.67,531.04 C51.1@1990.54,531.04 ; v1@1955.93,1042.02 C49.1@1991.04,1042.02 ; 2010,1976 2010,1939.84 2036.84,1913 U27.5@2059,1913 2112.68,1913 v1(2113.48,1913.81) ; v1(2132.58,1952.91) 2174.05,1952.91 U21.5@2174.18,1953.04
  Top Layer w20: C79.2@1682,910.5 v1(1799.5,910.5) ; C6.1@1743.31,269.31 Y1.4@1743.31,336.54 Y1.4@1753.15,346.38 ; v1(1946.53,530.89) v1@1946.67,531.04
  Bottom Layer w15: C77.2@2056.58,1907.53 2107.2,1907.53 v1(2113.48,1913.81) 2132.58,1932.91 v1(2132.58,1952.91) C64.2@2180.96,1952.91
  Bottom Layer w30: v1(1791,268) 1791,398 1923.89,530.89 v1(1946.53,530.89)
  other v1: 1896.18,1985.77 1934.18,1985.77 1974.18,1985.95 1894.18,2111.77 1932.18,2111.77 1972.18,2111.95
EVM_DVDD: C4.1 J1.50 | length 173.4
  Top Layer w10: v1(3267,636) 3269.95,638.95 J1.50@3351,638.95
  Bottom Layer w20: v1(3267,636) 3267.38,635.62 C4.1@3355,635.62
EVM_ID_PWR: C2.2 C5.1 J1.59 R6.2 U1.1 U1.8 | length 1432.7
  Top Layer w10: 3594,500 J1.59@3594,540.45 C5.1@3691.9,540.45
  Top Layer w12: U1.8@3083.39,331.81 3083.39,231.39 R6.2@3081.5,229.5 v1@3120,229.5 ; C2.2@3085.62,630 3083.39,627.76 U1.1@3083.39,558.19 v1(3134.19,558.19) ; C5.1@3691.9,540.45 C5.1@3692.5,541.05
  Top Layer w15: v1@3120,229.5 v1(3120,231) 3120,315 3178.59,373.59 3568.59,373.59 3594,399 3594,500
  Bottom Layer w12: v1(3120,231) 3120,544 v1(3134.19,558.19)
EVM_REG_5V5: C1.1 J1.1 | length 98.8
  Top Layer w8: C1.1@3691.8,1111.75 C1.1@3692.5,1111.05
  Top Layer w10: J1.1@3594,1111.75 C1.1@3691.8,1111.75
FB: C20.2 R25.1 R31.2 U5.6 | length 359.2
  Top Layer w25: R31.2@3265,2496 3265,2503 3264,2502 R31.2@3264,2495 C20.2@3264,2405 R25.1@3264,2315 3264,2301 3323,2242 U5.6@3323,2175.63
GND: C1.2 C2.1 C3.1 C4.2 C5.2 C21.2 C22.2 C23.2 C24.2 C27.2 C28.2 C29.2 C32.2 C34.1 C44.1 C58.1 C68.2 C73.1 C75.2 D4.1 J1.60 J1.MP1 J1.MP2 J1.MP3 J1.MP4 J2.2 J5.2 R34.1 R36.1 R41.1 R43.1 R45.1 R47.1 R49.1 R51.1 R53.1 R55.1 R104.1 TP14.1 TP15.1 TP16.1 U1.2 U1.3 U1.4 U4.4 U5.4 U5.8 U7.7 U7.21 U11.2 U11.8 U19.2 U19.8 U22.9 U22.15 U25.4 | length 4265.9
  Top Layer w10: J1.60@3351,540.45 3399.45,540.45 3436.5,577.5 v1@3472.5,577.5
  Top Layer w12: v1(2994,630) C2.1@3038.38,630 3032.2,623.83 U1.3@3032.2,558.19 ; U1.4@3006.61,558.19 U1.3@3032.2,558.19 ; U1.2@3057.8,558.19 U1.3@3032.2,558.19
  Top Layer w15: C58.1@2897.62,1030 C58.1@2900,1027.62 ; C44.1@2897.62,1499 C44.1@2900,1496.62
  Top Layer w20: C75.2@2691.93,2785 2747.93,2729 v1(2823,2729) ; U25.4@2732.28,345 U25.4@2731.28,344 v1(2810,344) ; TP15.1@2795,85 v1(2916,85) ; U19.2@2811.01,1030 C58.1@2897.62,1030 ; U19.8@2811.01,1330 2810.63,1330.38 2810.63,1369 v1(2811.01,1369.38) ; U11.2@2811.01,1499 C44.1@2897.62,1499 ; U11.8@2811.01,1799 v1(2811.01,1840.01) ; v1(2812.01,470.62) 2812.39,471 2812.39,509.62 U22.9@2812.01,510 ; U22.15@2812.01,810 2900.62,810 2901,810.38 2939.62,810.38 v1(2940,810) ; v1(2859,152) 2858.62,151.62 C73.1@2858.62,195 C73.1@2859.62,194 ; v1(2890,2757) TP14.1@2890,2835 v1(3011,2835) ; C58.1@2900,1027.62 2900.38,1028 2939,1028 v1(2939.38,1027.62) ; C44.1@2900,1496.62 2900.38,1497 2939,1497 v1(2939.38,1496.62) ; C21.2@2939.91,2303 C21.2@2941.91,2305 ; C3.1@3068.62,169.5 3090,148.12 J2.2@3090,79.5 ; R36.1@3263.21,2583.35 3263.21,2577.74 3320,2520.96 v1(3320,2430) ; v1(3403,2383) 3404,2382 R34.1@3469,2382 ; 3423,2046.35 U5.4@3423,2175.63 v1(3423,2253) ; J1.MP4@3472.5,493.75 3473,494.25 v1(3473,578) 3472.5,577.5 J1.MP3@3472.5,701.25 3472,701.75 v1(3472,825) 3472.5,825.5 J1.MP2@3472.5,951.25 3473,951.75 v1(3473,1080) 3472.5,1080.5 J1.MP1@3472.5,1158.75 ; v1(3626,1191) v1(3626,1191) C1.2@3692.5,1191.05 ; C5.2@3692.5,461.05 3765.05,461.05 v1(3766,460.09) ; D4.1@3825,2481.5 3825,2536.99 v1(3825.5,2537.5)
  Top Layer w25: C75.2@2691.93,2785 2741.93,2835 2819.5,2835 ; v1(3054.27,2411) 3054.13,2411.13 U4.4@3054.13,2462.6 3087.4,2462.6 v1(3105,2445)
  Top Layer w30: C21.2@2941.91,2305 2941.91,2385.91 v1(2954,2398)
  Bottom Layer w10: v2(3090,1963.35) 3115.59,1937.76 U7.7@3115.59,1871.81
  Bottom Layer w20: v1(2817.5,1985) C34.1@2858.5,1985 ; v1(2817.5,2050) C29.2@2858.5,2050 2858.5,2084.57 C28.2@2818.07,2125 ; R53.1@2876.38,1880 2876.38,1845.62 v1(2892,1830) ; 2876.38,1894.81 R55.1@2876.38,1930 ; R104.1@2980.5,2560 v1(2980.5,2613.5) ; R51.1@2990,1741.38 R49.1@3040,1741.38 v1(3040,1699.11) ; v1(3090,1699.11) R47.1@3090,1741.38 ; v1(3105,2445) 3168.07,2381.93 C32.2@3168.07,2201 ; v1(3140,1699.11) R45.1@3140,1741.38 ; v1(3190,1699.11) R43.1@3190,1741.38 ; v1(3240,1699.11) R41.1@3240,1741.38 ; C4.2@3355,555.62 3450.62,555.62 v1(3473,578)
  other v1: 3361,1779 3425,1779 3489,1779 3572,1780 3636,1780 3700,1780 3361,1843 3425,1843 3489,1843 3572,1844 3636,1844 3700,1844 3361,1907 3425,1907 3489,1907 3572,1908 3636,1908 3700,1908 3361,1971 3425,1971 3489,1971 3572,1972 3636,1972 3700,1972 3764,1972 3838,1972 3500,2685 3542,2685 3500,2745 3542,2745
  other v2: 3090,1911.18 3037.83,1963.35 3142.17,1963.35 3090,2015.51
ISO_ADC_CONVST: R62.1 U11.12 U12.6 | length 332.4
  Top Layer w8: R62.1@2122.68,1625.77 2123.3,1626.39 U12.6@2222.32,1626.39 2311.39,1626.39 2334,1649 U11.12@2436.99,1649 U11.12@2430.99,1643
ISO_ADC_CSN: R68.1 U11.13 U12.5 | length 327
  Top Layer w8: R68.1@2122.68,1591.77 2137.18,1591.77 2156.06,1610.65 U12.5@2222.32,1610.65 2312.35,1610.65 2324,1599 U11.13@2436.99,1599
ISO_ADC_RVS: R76.1 U13.6 U19.12 | length 316.9
  Top Layer w8: R76.1@2120.54,1179.4 2121.16,1180.02 U13.6@2223.18,1180.02 2436.51,1180.02 2436.74,1180.25 U19.12@2436.99,1180
ISO_ADC_SCLK: R60.1 U11.14 U12.4 | length 349.1
  Top Layer w8: R60.1@2122.68,1556.77 2136.18,1556.77 2174.31,1594.9 U12.4@2222.32,1594.9 2299.1,1594.9 2345,1549 U11.14@2436.99,1549
ISO_ADC_SDI: R67.1 U13.4 U19.13 | length 324.6
  Top Layer w8: R67.1@2120.54,1147.4 2121.67,1148.53 U13.4@2223.18,1148.53 2309.47,1148.53 2328,1130 U19.13@2436.99,1130
ISO_ADC_SDO0: R66.1 U14.7 U22.3 | length 351.5
  Top Layer w8: R66.1@2124.18,708.27 2152.68,708.27 2172.31,688.64 U14.7@2222.82,688.64 2291.64,688.64 2363,760 U22.3@2437.99,760
ISO_ADC_SDO1: R58.1 U14.6 U22.4 | length 329.8
  Top Layer w8: R58.1@2124.18,674.27 2125.56,672.89 U14.6@2222.82,672.89 2315.89,672.89 2353,710 U22.4@2437.99,710
ISO_ADC_SDO2: R61.1 U14.5 U22.5 | length 321.6
  Top Layer w8: R61.1@2124.18,641.27 2150.68,641.27 2166.56,657.15 U14.5@2222.82,657.15 2435.14,657.15 U22.5@2437.99,660
ISO_ADC_SDO3: R63.1 U14.4 U22.6 | length 341
  Top Layer w8: R63.1@2124.18,607.27 2138.68,607.27 2172.81,641.4 U14.4@2222.82,641.4 2304.6,641.4 2336,610 U22.6@2437.99,610
ISO_ADC_SRESETN: R57.1 U11.11 U12.7 | length 346.8
  Top Layer w8: R57.1@2122.68,1663.77 2144.18,1663.77 2165.81,1642.14 U12.7@2222.32,1642.14 2298.14,1642.14 2355,1699 U11.11@2436.99,1699
ISO_SCL: J3.3 R16.1 R73.1 U2.8 U25.6 | length 1802.2
  Top Layer w8: U2.8@1045,260.2 1045,199.38 R16.1@1046.38,198 1046.38,93.62 1070.5,69.5 1899.5,69.5 J3.3@1930,100 1972,142 1972,234 2010,272 2303.5,272 R73.1@2335,303.5 2344.5,294 U25.6@2516.72,294
ISO_SDA: J3.2 R15.1 R75.1 U2.7 U25.7 | length 2764.7
  Top Layer w8: U2.7@1045,485.8 1045,546.62 R15.1@1046.38,548 771,548 737,514 737,210 893,54 1984,54 J3.2@2030,100 1990,140 1990,230.08 2016.42,256.5 2309.92,256.5 2312.46,259.04 R75.1@2335,236.5 2342.5,244 U25.7@2516.72,244
ISO_SYSCLK: R71.1 U13.7 U19.11 | length 338.3
  Top Layer w8: R71.1@2120.54,1214.4 2145.55,1214.4 2164.18,1195.77 U13.7@2223.18,1195.77 2304.77,1195.77 2339,1230 U19.11@2436.99,1230
LDO_IN_ISO: C15.1 C16.1 C19.1 C30.1 C31.1 C36.1 C37.1 C40.1 C41.1 J4.2 R22.2 TP10.1 TP11.1 U6.13 U6.15 U6.16 U8.13 U8.15 U8.16 U9.1 U10.1 | length 980.1
  Top Layer w10: U6.13@516.6,2280.06 558.87,2280.06 v1(568.07,2270.86) ; U8.13@1660.54,2477.27 1699.73,2477.27 v1(1706.42,2470.58) ; U8.15@1660.54,2528.45 1713.69,2528.45 C31.1@1750.5,2565.27
  Top Layer w25: C37.1@937.53,2621.34 C36.1@937.53,2697.37 ; U9.1@939.4,2542.13 C37.1@939.4,2617 ; U10.1@1168.4,2543.13 1168.4,2618.91 C41.1@1168.5,2619
  Top Layer w30: C36.1@935,2698.54 TP10.1@935,2835 ; TP11.1@1160,2835 1168.46,2826.54 C40.1@1168.46,2698 ; C41.1@1168.5,2619 C40.1@1168.46,2698
  Bottom Layer w10: v1(555,2363) 568.07,2349.93 v1(568.07,2270.86) v1@568.07,2266.86 ; v1(1706,2557) 1706.42,2556.58 v1(1706.42,2470.58)
NetC9_2: C9.2 R19.2 U3.3 | length 131.1
  Top Layer w8: C9.2@1299.13,300 1354.13,300 R19.2@1355.51,301.38 1383.38,301.38 1397.16,315.16 U3.3@1423.94,315.16
NetC10_2: C10.2 R19.1 U3.2 | length 131.1
  Top Layer w8: C10.2@1299.13,350 1354.13,350 R19.1@1355.51,348.62 1383.38,348.62 1397.16,334.84 U3.2@1423.94,334.84
NetC13_1: C13.1 C14.1 C17.1 C18.2 D1.1 D3.1 J4.1 R22.1 TP3.1
  other v1: 1974.79,2570.35 2011.79,2570.35
NetC25_1: C25.1 R23.1 | length 80.4
  Top Layer w20: R23.1@406.57,2455.86 406.57,2531.43 C25.1@410,2534.86
NetC26_2: C26.2 U6.14 | length 92.2
  Top Layer w10: U6.14@516.6,2305.65 607.98,2305.65 C26.2@608.57,2305.06
NetC27_1: C27.1 U5.5 | length 104.7
  Top Layer w20: C27.1@3371,2279.5 3373,2277.5 U5.5@3373,2175.63
NetC32_1: C32.1 R38.1 | length 102.2
  Bottom Layer w15: R38.1@3240,2124.5 3301.93,2186.43 C32.1@3301.93,2201
NetC33_1: C33.1 R39.1 | length 98.2
  Top Layer w20: C33.1@1559.93,2736 1560.5,2735.43 R39.1@1560.5,2638
NetC34_2: C34.2 U7.14 | length 78.6
  Bottom Layer w12: C34.2@2921.5,1985 2925.43,1988.94 U7.14@2998.46,1988.94
NetC35_2: C35.2 U8.14 | length 92.2
  Top Layer w12: U8.14@1660.54,2502.86 1751.91,2502.86 C35.2@1752.5,2502.27
NetC76_1: C76.1 R77.2 R78.2 R79.1 | length 333.5
  Top Layer w8: v1(1066,1165) 1107.5,1165 R78.2@1162.5,1110 R79.1@1229.5,1110
  Bottom Layer w8: C76.1@974.62,1206 985.5,1195.13 R77.2@985.5,1150 1051,1150 v1(1066,1165)
NetC76_2: C76.2 C82.2 C83.1 R77.1 R82.2 U30.2 | length 459.8
  Top Layer w8: R82.2@687.5,1120 714.5,1120 C82.2@759.5,1165 786,1138.5 C83.1@786,1103.62 ; U30.2@900.88,1089.84 841.16,1089.84 v1(826,1105) C83.1@787.38,1105 ; C83.1@786,1103.62 C83.1@787.38,1105 ; C83.1@786,1103.62 C83.1@787.38,1105
  Bottom Layer w8: v1(826,1105) 877.5,1105 R77.1@922.5,1150 922.5,1201.13 C76.2@927.38,1206
NetC80_1: C80.1 R81.2 U29.13 U29.14 | length 230.1
  Top Layer w10: 1562,951 1559.85,953.15 U29.13@1559.85,1000.13 U29.14@1579.54,1000.13
  Top Layer w20: 1562,951 R81.2@1562,906.62 1614.13,906.62 C80.1@1618,910.5 1618,935 1594,959
NetC81_1: C81.1 C85.1 R79.2 U29.9 | length 349.6
  Top Layer w8: C81.1@1294,1201 1292.5,1199.5 R79.2@1292.5,1110 1362,1110 C85.1@1369,1117 1378,1117 1410.16,1084.84 1534.2,1084.84 U29.9@1534.26,1084.78
NetC82_1: C82.1 U30.1 | length 101.4
  Top Layer w8: C82.1@822.5,1165 877.97,1109.53 U30.1@900.88,1109.53
NetC83_2: C83.2 C86.2 C93.2 R83.2 R92.1 U30.3 | length 461.1
  Top Layer w8: R83.2@687.5,1040 714.5,1040 C86.2@759.5,995 786,1021.5 C83.2@786,1056.38 787.38,1055 v1(826,1055) 841.16,1070.16 U30.3@900.88,1070.16
  Bottom Layer w8: v1(826,1055) 879.5,1055 R92.1@924.5,1010 932.38,1002.13 C93.2@932.38,954
NetC84_1: C84.1 J11.2 R83.1 R86.2 | length 589.8
  Top Layer w8: C84.1@553,1040 R83.1@624.5,1040
  Top Layer w30: R86.2@406.5,645 507,645 544,682 J11.2@544,839.25 ; J11.2@544,845.87 J11.2@544,840.87 J11.2@544,839.25 ; C84.1@546,1040 546,841.25 J11.2@544,839.25
NetC84_2: C84.2 J7.2 R80.2 R82.1 | length 573.6
  Top Layer w8: C84.2@546,1120 R82.1@624.5,1120
  Top Layer w30: 429.18,1515 515,1515 543,1487 J7.2@543,1389.87 546,1386.87 C84.2@546,1120 C84.2@545,1121
NetC85_2: C85.2 C91.1 R89.2 U29.10 | length 350.2
  Top Layer w8: C91.1@1296,953 1292.5,956.5 R89.2@1292.5,1045 1361,1045 C85.2@1369,1037 1377,1037 1405.16,1065.16 1534.2,1065.16 U29.10@1534.26,1065.09
NetC86_1: C86.1 U30.4 | length 101.4
  Top Layer w8: C86.1@822.5,995 826,995 881.47,1050.47 U30.4@900.88,1050.47
NetC87_1: C87.1 R85.1 | length 64.7
  Top Layer w20: R85.1@1473.5,1300 R85.1@1474,1299.5
  Top Layer w30: C87.1@1474,1235.5 R85.1@1474,1299.5
NetC88_1: C88.1 R90.2 U29.3 | length 166.4
  Top Layer w12: U29.3@1618.91,1149.74 1618.91,1186.96 1639.14,1207.2 1672.2,1207.2 1710,1245 C88.1@1710,1259
NetC92_1: C92.1 R91.1 U29.12 | length 185.4
  Top Layer w8: 1528.81,991.81 1534.26,997.26 U29.12@1534.26,1025.72
  Top Layer w20: C92.1@1455,906.5 1455.13,906.62 R91.1@1512,906.62 1512,975 1528.81,991.81
NetC93_1: C93.1 R88.2 R89.1 R92.2 | length 332.3
  Top Layer w8: v1(1066,990) 1107.5,990 R88.2@1162.5,1045 R89.1@1229.5,1045
  Bottom Layer w8: C93.1@979.62,954 979.62,1002.13 R92.2@987.5,1010 1046,1010 v1(1066,990)
NetC95_1: C95.1 R96.1 U33.1 | length 159
  Top Layer w15: U33.1@909.13,1672.6 909.13,1596.64 C95.1@897.5,1585 960.5,1585 R96.1@963,1582.5
NetC95_2: C95.2 R94.1 U33.4 | length 273.6
  Top Layer w15: U33.4@800.87,1747.4 835.6,1747.4 846,1737 846,1596.5 C95.2@834.5,1585 833.5,1584 R94.1@833.5,1518
NetC96_1: C96.1 R93.1 | length 73.4
  Top Layer w15: R93.1@1716.62,1422 C96.1@1788,1422 C96.1@1790,1422
NetC98_1: C98.1 R99.1 | length 101.2
  Top Layer w20: R99.1@1212.5,1289 1212.91,1289.41 C98.1@1212.91,1390
NetC101_1: C101.1 R97.1 R101.2 U33.3 | length 216.4
  Top Layer w15: U33.3@909.13,1747.4 989.41,1747.4 C101.1@989.5,1747.5 R101.2@1054.5,1747.5 1057.01,1750 R97.1@1124.5,1750
NetC102_1: C102.1 U32.3 | length 177.2
  Top Layer w15: C102.1@1250.56,1564.94 1290.94,1564.94 1341.27,1615.27 U32.3@1341.27,1680.88
NetD4_2: D4.2 R40.1 | length 53.3
  Top Layer w15: R40.1@3825,2346.5 3825,2399.76
NetJ1_16: J1.16 R1.2 | length 304.9
  Top Layer w8: R1.2@3176.12,1180.55 3180.45,1180.55 3262,1099 3262,1023.25 3311.41,973.85 J1.16@3351,973.85
NetJ1_18: J1.18 R2.2 | length 276.3
  Top Layer w8: R2.2@3176.12,1130.55 3180.45,1130.55 3244,1067 3244,1018.63 3308.48,954.15 J1.18@3351,954.15
NetJ1_20: J1.20 R3.2 | length 248.3
  Top Layer w8: R3.2@3176.12,1080.55 3181.45,1080.55 3225,1037 3225,1015 3305.55,934.45 J1.20@3351,934.45
NetJ1_22: J1.22 R4.2 | length 222.8
  Top Layer w8: R4.2@3176.12,1030.55 3180.45,1030.55 3296.25,914.75 J1.22@3351,914.75
NetJ1_24: J1.24 R5.2 | length 210.3
  Top Layer w8: R5.2@3176.12,980.55 3180.45,980.55 3265.95,895.05 J1.24@3351,895.05
NetJ1_28: J1.28 R7.2 | length 205.9
  Top Layer w8: R7.2@3176.12,930.55 3251.02,855.65 J1.28@3351,855.65
NetJ1_30: J1.30 J1.32 J1.34 R8.2 | length 334.3
  Top Layer w8: R8.2@3176.12,880.55 3180.45,880.55 3244.75,816.25 3292.75,816.25 ; J1.34@3351,796.55 3312.45,796.55 3292.75,816.25 ; J1.32@3351,816.25 3292.75,816.25 ; J1.30@3351,835.95 3312.45,835.95 3292.75,816.25
NetJ1_38: J1.38 R9.2 | length 205.3
  Top Layer w8: R9.2@3176.12,830.55 3249.52,757.15 J1.38@3351,757.15
NetJ1_40: J1.40 R10.2 | length 192.7
  Top Layer w8: R10.2@3176.12,780.55 3219.22,737.45 J1.40@3351,737.45
NetJ1_42: J1.42 R11.2 | length 180.3
  Top Layer w8: R11.2@3176.62,732 3190.88,717.75 J1.42@3351,717.75
NetJ1_44: J1.44 R12.2 | length 182.1
  Top Layer w8: R12.2@3176.12,680.55 3193.62,698.05 J1.44@3351,698.05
